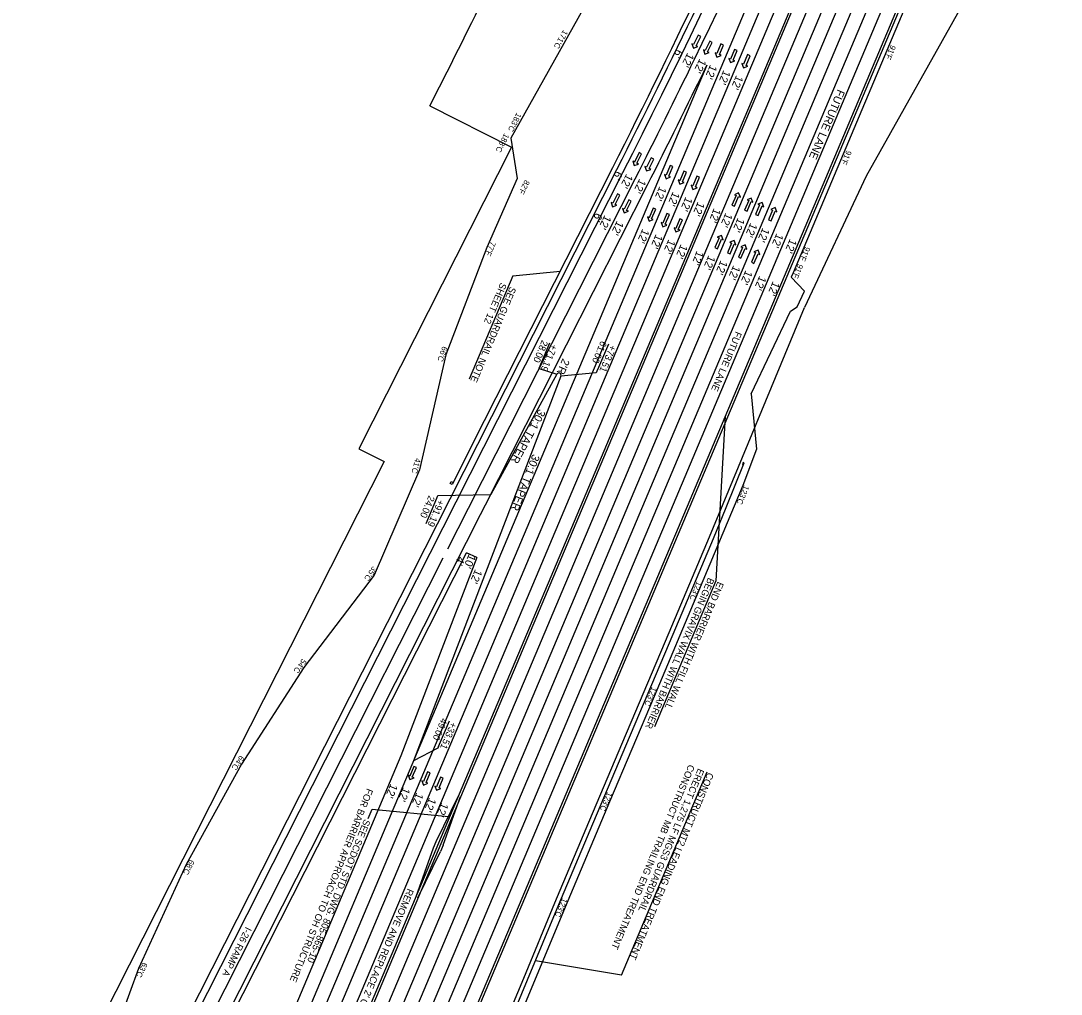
# Model space of a CAD drawing. Extents: x 1966090 to 1975830, y 788086 to 801233.
# Drawn here: x 1966602 to 1967511, y 792766 to 793617 of the extents above; entities that cross this region are included whole.
import ezdxf

# ---------------------------------------------------------------- set-up
doc = ezdxf.new("R2010")
doc.units = 0
for name, color, linetype in [('BR_PRESTRESSED BEAM', 7, 'Continuous'), ('BR_PROPOSED_DRAINAGE', 7, 'Continuous'), ('BR_REBAR', 7, 'Continuous'), ('RD_EX_Driveway_txCode', 7, 'Continuous'), ('RD_EX_RW_TX', 7, 'Continuous'), ('RD_EX_SU_Gas', 7, 'Continuous'), ('RD_EX_SU_H2O', 7, 'Continuous'), ('RD_EX_TX_Dam_ELEV', 7, 'Continuous'), ('RD_PD_PaveShd', 7, 'Continuous'), ('RD_Sketch6', 7, 'Continuous'), ('RD_Sketch8', 7, 'Continuous'), ('RD_Sketch9', 7, 'Continuous')]:
    doc.layers.add(name, color=color, linetype=linetype)

msp = doc.modelspace()

# ---------------------------------------------------------------- linework, layer by layer
at = {"layer": 'BR_PRESTRESSED BEAM'}
for p, q in [((1966996.8, 793247.44), (1967119.12, 793488.94)), ((1966996.8, 793247.44), (1966978.72, 793211.76)), ((1967218.3, 793191.61), (1967233.97, 793230.57)), ((1967233.05, 793230.95), (1967232.53, 793229)), ((1967232.53, 793229), (1967233.23, 793228.72)), ((1967233.97, 793230.57), (1967233.05, 793230.95)), ((1967233.23, 793228.72), (1967233.97, 793230.57)), ((1966976.94, 793212.66), (1966977.84, 793214.45)), ((1966978.72, 793211.76), (1966976.94, 793212.66)), ((1966977.84, 793214.45), (1966979.63, 793213.54)), ((1966979.63, 793213.54), (1966978.72, 793211.76))]:
    msp.add_line(p, q, dxfattribs=at)
msp.add_lwpolyline([(1966727.54, 792014.88), (1966739.33, 792045), (1966780.55, 792149.22), (1966780.57, 792149.28), (1966811.44, 792224.88), (1966840.84, 792295.42), (1966881.11, 792390.55), (1966902.01, 792440.03), (1966926.6, 792497.65), (1966945.07, 792541.99), (1966981.45, 792627.94), (1967013.45, 792703.58), (1967044.69, 792778.76), (1967071.94, 792844.43), (1967099.31, 792909.48), (1967127.2, 792975.7), (1967171.82, 793081.01), (1967207.07, 793164.47), (1967218.3, 793191.61)], dxfattribs=at)
msp.add_arc((1960883.39, 796647.38), 6990, 333.137426, 336.18058, dxfattribs=at)
at = {"layer": 'BR_PROPOSED_DRAINAGE'}
for p, q in [((1967378.4, 793637.72), (1967276.79, 793396.74)), ((1967096.64, 793633.73), (1967029.97, 793514.51)), ((1967029.97, 793514.51), (1967035.4, 793479.36)), ((1967008.95, 793419.04), (1966973.21, 793325.04)), ((1967276.79, 793396.74), (1967275.18, 793392.91)), ((1967286.6, 793380.69), (1967275.18, 793392.91)), ((1967280.38, 793367.03), (1967286.6, 793380.69)), ((1967240.18, 793291.06), (1967274.48, 793363.25)), ((1967274.48, 793363.25), (1967280.38, 793367.03)), ((1966973.21, 793325.04), (1966950.19, 793224.61)), ((1966950.19, 793224.61), (1966910.61, 793132.56)), ((1967232.72, 793210.78), (1967194.15, 793118.52)), ((1966910.61, 793132.56), (1966848.88, 793051.73)), ((1967194.15, 793118.52), (1967155.19, 793026.42)), ((1966848.88, 793051.73), (1966794.58, 792967.14)), ((1967155.19, 793026.42), (1967116.26, 792934.31)), ((1966794.58, 792967.14), (1966746.03, 792879.63)), ((1967116.26, 792934.31), (1967077.46, 792842.14)), ((1966746.03, 792879.63), (1966704.51, 792788.56)), ((1967077.46, 792842.14), (1967039.13, 792749.78)), ((1966704.51, 792788.56), (1966669.48, 792693.76))]:
    msp.add_line(p, q, dxfattribs=at)
for points in [[(1967035.4, 793479.36), (1967008.95, 793419.04)], [(1967240.18, 793291.06), (1967244.77, 793242.54), (1967232.72, 793210.78)]]:
    msp.add_lwpolyline(points, dxfattribs=at)
at = {"layer": 'BR_REBAR'}
for p, q in [((1967372.88, 793640.05), (1966736.08, 792129.8)), ((1967374.72, 793639.28), (1966737.92, 792129.02))]:
    msp.add_line(p, q, dxfattribs=at)
at = {"layer": 'RD_EX_Driveway_txCode'}
for points in [[(1967196.02, 793603.46), (1967193.87, 793604.52), (1967189.82, 793596.29), (1967188.36, 793597.01), (1967189.64, 793593.22), (1967193.43, 793594.51), (1967191.97, 793595.23)], [(1967206, 793598.23), (1967203.85, 793599.29), (1967199.8, 793591.06), (1967198.34, 793591.78), (1967199.63, 793588), (1967203.41, 793589.29), (1967201.95, 793590.01)], [(1967215.86, 793595.94), (1967213.65, 793596.88), (1967210.07, 793588.43), (1967208.57, 793589.07), (1967210.06, 793585.36), (1967213.77, 793586.86), (1967212.27, 793587.5)], [(1967227.83, 793591.13), (1967225.62, 793592.07), (1967222.04, 793583.63), (1967220.54, 793584.26), (1967222.03, 793580.55), (1967225.74, 793582.05), (1967224.25, 793582.69)], [(1967239.2, 793586.56), (1967236.99, 793587.5), (1967233.4, 793579.06), (1967231.9, 793579.7), (1967233.4, 793575.99), (1967237.11, 793577.49), (1967235.61, 793578.12)], [(1967144.26, 793500.79), (1967142.11, 793501.85), (1967138.06, 793493.62), (1967136.6, 793494.34), (1967137.89, 793490.56), (1967141.68, 793491.84), (1967140.21, 793492.56)], [(1967154.88, 793496.18), (1967152.72, 793497.24), (1967148.67, 793489.01), (1967147.21, 793489.73), (1967148.5, 793485.94), (1967152.29, 793487.23), (1967150.83, 793487.95)], [(1967171.56, 793489.65), (1967169.35, 793490.58), (1967165.76, 793482.14), (1967164.26, 793482.78), (1967165.76, 793479.07), (1967169.47, 793480.57), (1967167.97, 793481.2)], [(1967183.53, 793484.84), (1967181.32, 793485.78), (1967177.73, 793477.34), (1967176.23, 793477.97), (1967177.73, 793474.26), (1967181.44, 793475.76), (1967179.94, 793476.4)], [(1967194.89, 793480.27), (1967192.69, 793481.21), (1967189.1, 793472.77), (1967187.6, 793473.41), (1967189.1, 793469.7), (1967192.81, 793471.2), (1967191.31, 793471.83)], [(1967125.31, 793464.77), (1967123.16, 793465.83), (1967119.11, 793457.6), (1967117.65, 793458.32), (1967118.94, 793454.54), (1967122.72, 793455.83), (1967121.26, 793456.55)], [(1967223.34, 793456), (1967225.55, 793455.06), (1967229.13, 793463.5), (1967230.63, 793462.86), (1967229.14, 793466.57), (1967225.43, 793465.08), (1967226.93, 793464.44)], [(1967135.29, 793459.55), (1967133.14, 793460.61), (1967129.09, 793452.38), (1967127.63, 793453.1), (1967128.92, 793449.31), (1967132.71, 793450.6), (1967131.24, 793451.32)], [(1967234.39, 793451.56), (1967236.6, 793450.62), (1967240.18, 793459.06), (1967241.68, 793458.43), (1967240.18, 793462.14), (1967236.47, 793460.64), (1967237.97, 793460)], [(1967243.92, 793447.73), (1967246.13, 793446.79), (1967249.72, 793455.23), (1967251.22, 793454.6), (1967249.72, 793458.31), (1967246.01, 793456.81), (1967247.51, 793456.17)], [(1967255.27, 793443.17), (1967257.48, 793442.23), (1967261.07, 793450.68), (1967262.57, 793450.04), (1967261.07, 793453.75), (1967257.36, 793452.25), (1967258.86, 793451.61)], [(1967156.63, 793452.47), (1967154.42, 793453.41), (1967150.83, 793444.96), (1967149.33, 793445.6), (1967150.83, 793441.89), (1967154.54, 793443.39), (1967153.04, 793444.03)], [(1967168.6, 793447.66), (1967166.39, 793448.6), (1967162.8, 793440.16), (1967161.3, 793440.79), (1967162.8, 793437.08), (1967166.51, 793438.58), (1967165.01, 793439.22)], [(1967179.96, 793443.09), (1967177.75, 793444.03), (1967174.17, 793435.59), (1967172.67, 793436.23), (1967174.17, 793432.52), (1967177.88, 793434.02), (1967176.38, 793434.65)], [(1967208.41, 793418.82), (1967210.62, 793417.88), (1967214.2, 793426.32), (1967215.7, 793425.69), (1967214.2, 793429.39), (1967210.5, 793427.9), (1967211.99, 793427.26)], [(1967219.46, 793414.38), (1967221.66, 793413.44), (1967225.25, 793421.89), (1967226.75, 793421.25), (1967225.25, 793424.96), (1967221.54, 793423.46), (1967223.04, 793422.82)], [(1967228.99, 793410.55), (1967231.2, 793409.61), (1967234.79, 793418.06), (1967236.28, 793417.42), (1967234.79, 793421.13), (1967231.08, 793419.63), (1967232.58, 793418.99)], [(1967240.34, 793405.99), (1967242.55, 793405.06), (1967246.14, 793413.5), (1967247.63, 793412.86), (1967246.14, 793416.57), (1967242.43, 793415.07), (1967243.93, 793414.44)], [(1966947.44, 792964.36), (1966945.23, 792965.3), (1966941.64, 792956.86), (1966940.15, 792957.5), (1966941.64, 792953.79), (1966945.35, 792955.29), (1966943.85, 792955.92)], [(1966959.41, 792959.56), (1966957.2, 792960.49), (1966953.62, 792952.05), (1966952.12, 792952.69), (1966953.61, 792948.98), (1966957.32, 792950.48), (1966955.82, 792951.11)], [(1966970.78, 792954.99), (1966968.57, 792955.93), (1966964.98, 792947.49), (1966963.48, 792948.13), (1966964.98, 792944.42), (1966968.69, 792945.91), (1966967.19, 792946.55)]]:
    msp.add_lwpolyline(points, close=True, dxfattribs=at)
at = {"layer": 'RD_EX_SU_Gas'}
for p, q in [((1967295.48, 793770.5), (1966623.67, 792177.2)), ((1967306.53, 793765.84), (1966634.72, 792172.54)), ((1967352.6, 793746.41), (1966680.8, 792153.11)), ((1967374.72, 793737.08), (1966702.91, 792143.79)), ((1967363.66, 793741.75), (1966804.36, 792415.28)), ((1966740.54, 792692.82), (1966970.93, 793147.68))]:
    msp.add_line(p, q, dxfattribs=at)
at = {"layer": 'RD_EX_TX_Dam_ELEV'}
for p, q in [((1967511.15, 793784.92), (1967340.75, 793481.38)), ((1966959.19, 793542.88), (1967030.6, 793506.72)), ((1967030.6, 793506.72), (1966897.01, 793242.98)), ((1967340.75, 793481.38), (1967286.61, 793366.33)), ((1966897.01, 793242.98), (1966919.32, 793231.68)), ((1966919.32, 793231.68), (1966666.96, 792733.45))]:
    msp.add_line(p, q, dxfattribs=at)
msp.add_lwpolyline([(1966777.11, 792150.72), (1966807.98, 792226.31), (1966837.38, 792296.88), (1966877.65, 792392.01), (1966898.55, 792441.49), (1966923.15, 792499.11), (1966941.61, 792543.44), (1966978, 792629.4), (1967009.99, 792705.03), (1967041.23, 792780.2), (1967068.47, 792845.88), (1967095.85, 792910.94), (1967123.75, 792977.16), (1967168.36, 793082.47), (1967203.61, 793165.92), (1967286.61, 793366.33)], dxfattribs=at)
msp.add_arc((1960883.39, 796647.38), 6823, 332.934754, 334.920676, dxfattribs=at)
at = {"layer": 'RD_PD_PaveShd'}
for p, q in [((1967328.65, 793756.51), (1966656.84, 792163.21)), ((1967330.49, 793755.73), (1966658.68, 792162.44)), ((1967372.88, 793640.05), (1966736.08, 792129.8)), ((1966976.84, 793199.18), (1967122.68, 793487.13)), ((1966724.48, 792700.95), (1966976.84, 793199.18)), ((1966754.81, 792685.59), (1966991.11, 793152.11)), ((1967000.26, 793148.04), (1966933.86, 792974.64)), ((1967000.26, 793148.04), (1966991.11, 793152.11)), ((1966933.86, 792974.64), (1966601.55, 792186.52))]:
    msp.add_line(p, q, dxfattribs=at)
msp.add_arc((1960883.39, 796647.38), 6994, 333.137426, 335.745551, dxfattribs=at)
at = {"layer": 'RD_Sketch6'}
for p, q in [((1967031.73, 793394.1), (1966993.59, 793303.76)), ((1967031.73, 793394.1), (1967073.24, 793398.36)), ((1967054.78, 793313.31), (1967064.13, 793335.45)), ((1967106.01, 793312.21), (1967115.55, 793334.8)), ((1967217.47, 793271.48), (1967209.29, 793127.47)), ((1966955.82, 793177.49), (1966965.16, 793199.63)), ((1967209.29, 793127.47), (1967155.47, 792999.83)), ((1966966.71, 792982.54), (1966976.25, 793005.13)), ((1967126.78, 792782.83), (1967201.64, 792960.38)), ((1966905.18, 792919.76), (1966908.63, 792927.94)), ((1966908.63, 792927.94), (1966975.36, 792921.55)), ((1967126.78, 792782.83), (1967051.52, 792795.21))]:
    msp.add_line(p, q, dxfattribs=at)
for points in [[(1967054.78, 793313.31), (1967054.7, 793313.12), (1967070.18, 793308.22)], [(1967105.89, 793312.26), (1967104.7, 793309.43), (1967073.8, 793306.54)], [(1966965.16, 793199.63), (1966966.16, 793201.98), (1967012.39, 793202.98)], [(1966966.71, 792982.54), (1966966.12, 792981.14), (1966944.99, 792970.16)]]:
    msp.add_lwpolyline(points, dxfattribs=at)
at = {"layer": 'RD_Sketch8'}
for p, q in [((1967317.59, 793761.17), (1966645.78, 792167.88)), ((1967341.55, 793751.07), (1966669.74, 792157.77)), ((1967396.83, 793727.76), (1966725.02, 792134.46)), ((1967385.78, 793732.42), (1966830.52, 792415.56)), ((1967201.48, 793578.46), (1966933.32, 792942.47)), ((1966982.19, 793196.47), (1967128.04, 793484.42)), ((1966992.9, 793191.05), (1967138.74, 793478.99)), ((1967007.85, 793194.01), (1967149.45, 793473.57)), ((1967070.18, 793308.22), (1967012.39, 793202.98)), ((1967073.8, 793306.54), (1966944.99, 792970.16)), ((1966729.83, 792698.24), (1966982.19, 793196.47)), ((1966974.83, 793155.38), (1966992.9, 793191.05)), ((1967003.6, 793185.63), (1967007.85, 793194.01)), ((1966751.24, 792687.4), (1967003.6, 793185.63)), ((1966933.32, 792942.47), (1966612.61, 792181.86))]:
    msp.add_line(p, q, dxfattribs=at)
for centre, radius, start, end in [((1960883.39, 796647.38), 7000, 333.137426, 338.119008), ((1960883.39, 796647.38), 7012, 334.092011, 338.119008), ((1960883.39, 796647.38), 7012, 333.137426, 334.092526), ((1960883.39, 796647.38), 7024, 333.137426, 334.092526), ((1967071.94, 793307.26), 2, 338.89982, 151.37503)]:
    msp.add_arc(centre, radius, start, end, dxfattribs=at)
at = {"layer": 'RD_Sketch9'}
for p, q in [((1966984.22, 792939.69), (1966964.44, 792899.19)), ((1966970.89, 792896.47), (1966986.07, 792938.91)), ((1966964.44, 792899.19), (1966962.1, 792893.67)), ((1966962.1, 792893.67), (1966946.92, 792851.23)), ((1966948.77, 792850.45), (1966968.55, 792890.95)), ((1966970.89, 792896.47), (1966968.55, 792890.95))]:
    msp.add_line(p, q, dxfattribs=at)

# ---------------------------------------------------------------- texts
at = {"layer": 'RD_EX_Driveway_txCode'}
for s, height, rotation, p in [("6'", 7, 243.22701, (1967174.67, 793592.71)), ("12'", 7, 243.22701, (1967184.43, 793589.57)), ("12'", 7, 243.22701, (1967195.11, 793584.37)), ("12'", 7, 246.98102, (1967204.32, 793579.1)), ("12'", 7, 246.98102, (1967215.99, 793574.41)), ("12'", 7, 246.98102, (1967227.14, 793569.93)), ("6'", 7, 244.68162, (1967121.74, 793486.33)), ("12'", 7, 243.22701, (1967131.04, 793483.71)), ("12'", 7, 243.22701, (1967142.46, 793479.37)), ("12'", 7, 246.98102, (1967160.02, 793472.8)), ("12'", 7, 246.98102, (1967171.69, 793468.12)), ("12'", 7, 246.98102, (1967182.84, 793463.64)), ("12'", 7, 246.98102, (1967193.52, 793459.35)), ("6'", 7, 244.68162, (1967104.16, 793449.73)), ("12'", 7, 243.22701, (1967112.09, 793447.7)), ("12'", 7, 248.93723, (1967207.5, 793453.65)), ("12'", 7, 246.98102, (1967217.75, 793449.62)), ("12'", 7, 246.98102, (1967228.44, 793445.33)), ("12'", 7, 243.22701, (1967122.87, 793442.75)), ("12'", 7, 246.98102, (1967239.51, 793440.88)), ("12'", 7, 246.98102, (1967250.18, 793436.59)), ("12'", 7, 246.98102, (1967145.09, 793435.63)), ("12'", 7, 246.98102, (1967156.76, 793430.94)), ("12'", 7, 246.98102, (1967262.29, 793431.73)), ("12'", 7, 246.98102, (1967274.08, 793427)), ("12'", 7, 246.98102, (1967167.9, 793426.46)), ("12'", 7, 246.98102, (1967178.59, 793422.17)), ("12'", 7, 248.93723, (1967192.56, 793416.47)), ("12'", 7, 246.98102, (1967202.82, 793412.44)), ("12'", 7, 246.98102, (1967213.51, 793408.15)), ("12'", 7, 246.98102, (1967224.57, 793403.7)), ("12'", 7, 246.98102, (1967235.25, 793399.42)), ("12'", 7, 246.98102, (1967247.36, 793394.55)), ("12'", 7, 246.98102, (1967259.14, 793389.82)), ("2'R", 7, 246.92483, (1967075.31, 793322.32)), ('30:1 TAPER', 7, 241.41081, (1967054.58, 793278.13)), ('30:1 TAPER', 7, 248.11285, (1967049.12, 793238.66)), ("4'", 7, 242.54925, (1966984.21, 793149.54)), ("10'", 7, 246.92483, (1966993.33, 793151.35)), ("12'", 7, 246.841, (1966998.92, 793138.1)), ("12'", 7, 246.98102, (1966924.99, 792950.61)), ("12'", 7, 246.98102, (1966935.9, 792947.52)), ("12'", 7, 246.98102, (1966947.57, 792942.83)), ("12'", 7, 246.98102, (1966958.72, 792938.36)), ("12'", 7, 246.98102, (1966969.4, 792934.07)), ("REMOVE AND REPLACE 2' CONCRETE MEDIAN BARRIER", 5.9996, 247.4535, (1966939.77, 792858.91))]:
    msp.add_text(s, height=height, rotation=rotation, dxfattribs=at).set_placement(p)
at = {"layer": 'RD_EX_RW_TX'}
for s, rotation, p in [("171'C", 239.91122, (1967075.96, 793609.5)), ("91'F", 247.13743, (1967362.17, 793596.34)), ("183'C", 243.13743, (1967035.09, 793537.14)), ("183'C", 243.13743, (1967024.36, 793519.06)), ("91'F", 247.13743, (1967323.53, 793504.25)), ("82'F", 243.13743, (1967042.37, 793478.44)), ("77'F", 247.14928, (1967012.42, 793424.54)), ("91'F", 247.13743, (1967287.44, 793420.09)), ("91'F", 247.13743, (1967281.13, 793404.98)), ("66'C", 250.0024, (1966970.21, 793332.96)), ("41'C", 255.17049, (1966946.56, 793235.21)), ("123'C", 247.13743, (1967233.97, 793211.41)), ("35'C", 233.90965, (1966909.37, 793140.66)), ("123'C", 247.13743, (1967192.74, 793127.41)), ("54'C", 233.44934, (1966847.73, 793059.85)), ("123'C", 247.13743, (1967153.33, 793035.18)), ("64'C", 235.00117, (1966793.26, 792975.3)), ("123'C", 247.13743, (1967114.35, 792943.29)), ("68'C", 243.13743, (1966749.25, 792884.19)), ("123'C", 247.13743, (1967074.97, 792850.61)), ("63'C", 243.13743, (1966708.25, 792794.41))]:
    msp.add_text(s, height=5, rotation=rotation, dxfattribs=at).set_placement(p)
at = {"layer": 'RD_EX_SU_H2O'}
for s, height, rotation, p in [('FUTURE LANE', 7, 246.98102, (1967315.86, 793557.65)), ('FUTURE LANE', 5.9996, 247.1375, (1967226.62, 793346.03)), ('I-26 RAMP A', 5.9996, 243.74162, (1966798.23, 792825.43))]:
    msp.add_text(s, height=height, rotation=rotation, dxfattribs=at).set_placement(p)
at = {"layer": 'RD_Sketch6'}
for s, height, rotation, p in [('SEE GUARDRAIL NOTE', 5.9996, 247.13743, (1967029.29, 793385.12)), ('SHEET 12', 6, 247.13743, (1967021, 793388.62)), ('28.00', 6, 247.11083, (1967057.22, 793338.36)), ('61.00', 6, 247.11083, (1967108.64, 793337.72)), ('+71.19', 6, 247.11083, (1967065.51, 793334.86)), ('+73.51', 6, 247.11083, (1967116.93, 793334.21)), ('24.00', 6, 247.11083, (1966958.25, 793202.55)), ('+91.19', 6, 247.11083, (1966966.54, 793199.04)), ('BEGIN GRAVIX WALL WITH BARRIER', 5.9996, 247.14996, (1967202.57, 793130.73)), ('END BARRIER WITH FILL WALL', 5.9996, 247.14996, (1967210.86, 793127.24)), ('49.00', 6, 247.11083, (1966969.34, 793008.04)), ('+33.51', 6, 247.11083, (1966977.63, 793004.54)), ('CONSTRUCT MB TRAILING END TREATMENT', 5.9996, 247.10833, (1967185.46, 792967.42)), ('ERECT 1,275 LF MGS3 GUARDRAIL', 5.9996, 247.10833, (1967193.76, 792963.92)), ('CONSTRUCT MT2 LEADING END TREATMENT', 5.9996, 247.10833, (1967202.05, 792960.42)), ('FOR BARRIER APPROACH TO OH STRUCTURE', 6, 248.11901, (1966904.15, 792946.52)), ('SEE SCDOT STD. DWG. 805-865-10', 6, 248.11901, (1966901.79, 792919.53))]:
    msp.add_text(s, height=height, rotation=rotation, dxfattribs=at).set_placement(p)

doc.saveas('drawing.dxf')
